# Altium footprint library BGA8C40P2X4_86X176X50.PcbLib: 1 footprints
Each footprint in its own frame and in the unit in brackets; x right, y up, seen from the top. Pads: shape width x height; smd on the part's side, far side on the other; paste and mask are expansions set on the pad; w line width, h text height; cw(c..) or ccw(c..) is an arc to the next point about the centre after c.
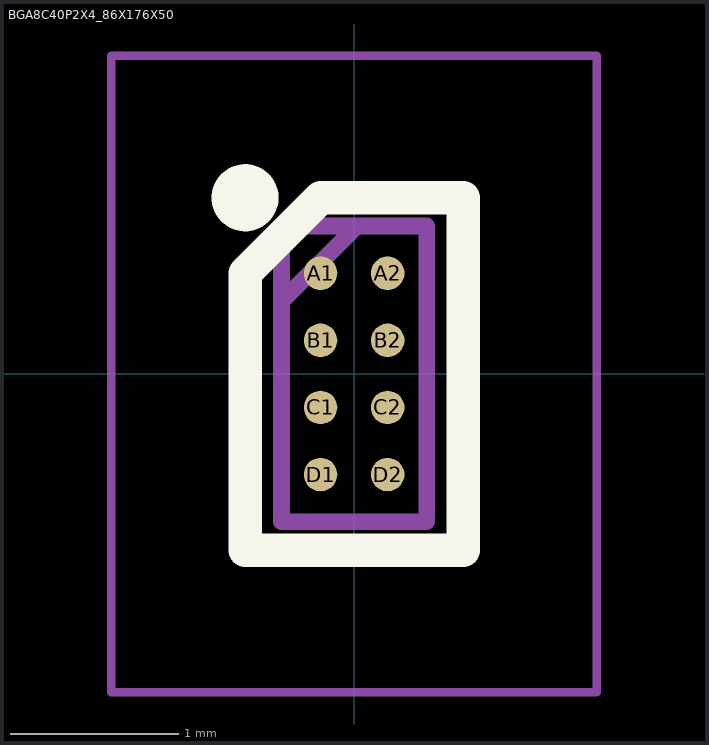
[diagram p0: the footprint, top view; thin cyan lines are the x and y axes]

## BGA8C40P2X4_86X176X50 [mm]
pads (8):
  round 0.2 smd: A1(-0.2,0.6) A2(0.2,0.6) B1(-0.2,0.2) B2(0.2,0.2) C1(-0.2,-0.2) C2(0.2,-0.2) D1(-0.2,-0.6) D2(0.2,-0.6)
Top Overlay:
  circle w0.2: c-0.65,1.05 r0.1
  lines w0.2: -0.65,-1.05 0.65,-1.05 0.65,1.05 -0.2,1.05 -0.65,0.6 -0.65,-1.05
Mechanical 15:
  lines w0.1: -0.432,0.433 0.016,0.881 ; -0.432,-0.881 0.433,-0.881 0.433,0.882 -0.432,0.882 -0.432,-0.881
Mechanical 20:
  lines w0.05: -1.448,-1.897 1.447,-1.897 1.447,1.896 -1.448,1.896 -1.448,-1.897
